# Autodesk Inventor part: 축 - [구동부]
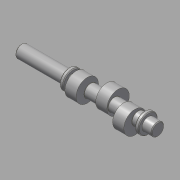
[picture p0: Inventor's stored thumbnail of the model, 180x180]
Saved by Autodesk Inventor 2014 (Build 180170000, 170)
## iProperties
Company: 한국ATC센터
Created: 2014-08
Part Number: 축 - [구동부]
Document SubType Name: Modeling
Designer: KYOUNG IL JANG
Density: 7.86 g/cm^3
Material: 강철, 연강
Appearance: 강철
Mass: 516.584 g
Surface Area: 162.516 cm^2
Volume: 65.7231 cm^3
Author: KYOUNG IL JANG
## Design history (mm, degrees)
sketch "스케치1"
  geometry: L1 (-91.5, 0)-(91.5, 0); L2 (-91.5, 0)-(-91.5, 8.5); L3 (-91.5, 8.5)-(-27.5, 8.5); L4 (-27.5, 8.5)-(-27.5, 13); L5 (-27.5, 13)-(-22.5, 13); L6 (-22.5, 13)-(-22.5, 8.5); L7 (-22.5, 8.5)-(73.5, 8.5); L8 (73.5, 8.5)-(73.5, 13); L9 (73.5, 13)-(78.5, 13); L10 (78.5, 13)-(78.5, 8.5); L11 (78.5, 8.5)-(91.5, 8.5); L12 (91.5, 8.5)-(91.5, 0); 2 further points
  constraints: 24 end point, 5 parallel, 1 coincident, 1 horizontal, 1 midpoint, 1 perpendicular
  dimensions: "d0" = 183 distance of L1.start L1.end (derived); "d2" = 17 diameter of L3 L1; "d3" = 26 diameter of L5 L1; "d4" = 17 diameter of L7 L1; "d5" = 26 diameter of L9 L1; "d6" = 17 diameter of L11 L1; "d7" = 5 distance of L8.end L9.end; "d8" = 5 distance of L4.end L5.end; "d10" = 64 distance of L2.end L3.end; "d11" = 13 distance of L10.end L11.end; "d35" = 96 distance between parallel lines of L8 L6
revolve "회전1" sketch "스케치1" stored, may be unused: angle "d12" = 90 deg
node "작업 평면7"
sketch "스케치6"
  geometry: C1 r 15 at (0, 5); 1 further point
  constraints: 1 centre point, 1 vertical alignment
  dimensions: "d37" = 30 diameter of C1; "d38" = 5 distance of C1.centre point (0, 0)
extrude "돌출4" join sketch "스케치6" stored distance "d33" = 15; taper "d34" = 0 deg
node "작업 평면8"
sketch "스케치7"
  geometry: L1 (0, 0)-(-6.5, -11.258); L2 (0, 0)-(13, 0); C1 r 15 at (-2.5, -4.33); A1 r 13 centre (0, 0) between (-6.5, -11.258) and (13, 0) reference; 1 further point
  constraints: 4 end point, 2 point on circle, 1 centre point, 1 horizontal, 1 point on line
  dimensions: "d40" = 120 deg angle of L1 L2; "d41" = 30 diameter of C1; "d42" = 5 distance of point (0, 0) C1.centre
extrude "돌출5" join sketch "스케치7" stored distance "d43" = 15; taper "d44" = 0 deg
node "작업 평면9"
sketch "스케치8"
  geometry: L1 (0, 0)-(4.25, -7.361); L2 (0, 0)-(-8.5, 0); C1 r 15 at (2.5, -4.33); A1 r 8.5 centre (0, 0) between (4.25, -7.361) and (-8.5, 0) reference; 1 further point
  constraints: 4 end point, 2 point on circle, 1 centre point, 1 horizontal, 1 point on line
  dimensions: "d46" = 120 deg angle of L1 L2; "d47" = 30 diameter of C1; "d48" = 5 distance of point (0, 0) C1.centre
extrude "돌출6" join sketch "스케치8" stored distance "d49" = 15; taper "d50" = 0 deg
node "작업 평면3"
sketch "스케치5"
  geometry: L1 (32, 8.5)-(32, -8.5) reference; L2 (27.5, -2.5)-(14.5, -2.5); L3 (14.5, 2.5)-(27.5, 2.5); A1 r 2.5 centre (14.5, 0) between (14.5, 2.5) and (14.5, -2.5); A2 r 2.5 centre (27.5, 0) between (27.5, -2.5) and (27.5, 2.5); 4 further points
  constraints: 4 end point, 4 point on circle, 4 tangent, 2 centre point, 2 point on line, 1 horizontal alignment, 1 midpoint, 1 parallel, 1 perpendicular
  dimensions: "d23" = 5 distance between parallel lines of L3 L2; "d36" = 20 dimension on A1 L1; "d52" = 2 distance edge to line of A2 L1
extrude "돌출3" cut sketch "스케치5" distance "d25" = 3; taper "d26" = 0 deg
chamfer "모따기1" distance "d27" = 1; stored, may be unused: second distance "d28" = 2, angle "d29" = 45 deg
fillet "모깎기1" dims "d51" = 0.3
chamfer "모따기2" distance "d53" = 1; stored, may be unused: second distance "d54" = 2, angle "d55" = 45 deg
node "작업 평면10"
node "솔리드1"
other parameters: "d39" = -32, "d45" = 32
